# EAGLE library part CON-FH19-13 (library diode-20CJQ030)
Hirose FH19 & FH19S Series 0.5mm pitch, 0.9mm above the board, Flexible Printed Circuit & Flexible Flat Cable Connectors Features: 1. Low-profile 0.5mm pitch FPC, FFC Connectors Miniaturization of portable equipment and personal mobile devices has created increased demand for a low profile, high density, and high reliability connectors. *The design of this connector has been made thinner and smaller, with a height of 0.9mm and width of 3mm. [As of August 2002, this is the smallest connector of this type available on the market !] *PCB footprint: Reduced approximately 48% (as compared with Hirose Electric's 0.5mm pitch FH12 Series connectors) *Connector weight: Reduced approximately 78% (as compared with Hirose Electric's 0.5mm pitch FH12 Series connectors) 2. Conductive traces on the PCB can be designed to run under the connector All bottom surface of the connector is solid, without any exposure of the contact. 3. Proven Flip-Lock Actuator System assures easy and reliable operation Rotating actuator permits easy insertion and reliable connection with the FPC & FFC. Tactile sensation confirms complete mechanical locking of the actuator and the electrical connection. 4. Accepts 0.2mm & 0.3mm thick FPC, FFC Accepts 0.2mm & 0.3mm thick FPC, FFC, easy inserted in the connector. The connector will also terminate successfully with 0.2mm thick Flat Flexible Cable (FFC). 5. Designed for placement with automatic equipment Packaged in embossed tape, on reel. One reel contains 5,000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
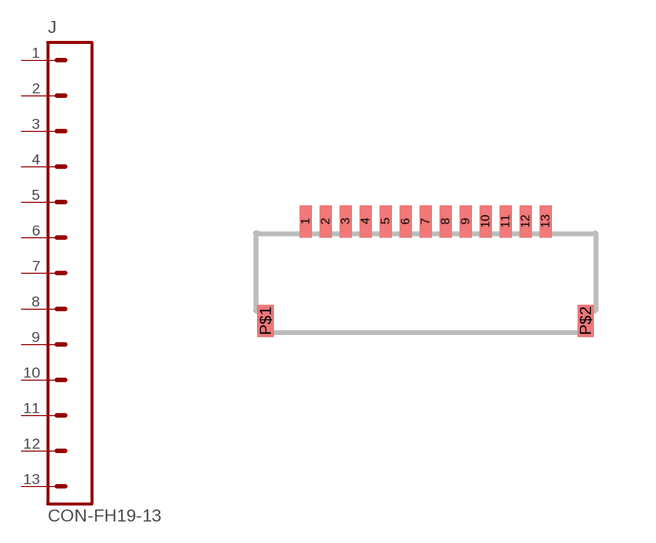
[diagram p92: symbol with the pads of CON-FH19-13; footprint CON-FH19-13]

Designator prefix J

## CON-FH19-13  [CON-FH19-13]
1  1  pas
2  2  pas
3  3  pas
4  4  pas
5  5  pas
6  6  pas
7  7  pas
8  8  pas
9  9  pas
10  10  pas
11  11  pas
12  12  pas
13  13  pas

## Footprint CON-FH19-13 (pad centres in mm)
Hirose FH19 13pin 0.5mm pitch FPC/FFC connector
smd 0.3 x 0.8: 1 -3,2.49; 2 -2.5,2.49; 3 -2,2.49; 4 -1.5,2.49; 5 -1,2.49; 6 -0.5,2.49; 7 0,2.49; 8 0.5,2.49; 9 1,2.49; 10 1.5,2.49; 11 2,2.49; 12 2.5,2.49; 13 3,2.49
smd 0.4 x 0.8: P$1 -4,0; P$2 4,0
